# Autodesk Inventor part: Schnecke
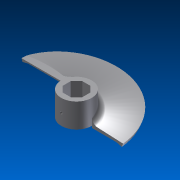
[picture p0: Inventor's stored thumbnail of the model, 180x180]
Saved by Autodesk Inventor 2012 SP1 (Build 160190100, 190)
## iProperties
Created: 2012-02
Part Number: Schnecke
Material: Default
Document SubType Name: Modeling
Designer: MP
Mass: 7789.64 g
Surface Area: 6560.61 cm^2
Volume: 7789.64 cm^3
Density: 1 g/cm^3
Author: MP
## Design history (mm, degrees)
sketch "Skizze1"
  geometry: L1 (0, 0)-(0, 200); L2 (0, 10)-(-285, 10); L3 (-285, 10)-(-325, 0); L4 (-325, 0)-(-334.295, 25); L5 (-334.295, 25)-(-110, 35); L6 (-110, 35)-(-110, 10); L7 (-110, 35)-(-110, 200); L8 (-110, 200)-(0, 200); L9 (-285, 10)-(-328.718, 10); L10 (-110, 35)-(0, 39.904); L11 (-25, 38.79)-(-25, 10); L12 (0, 25)-(-110, 25); 1 further point
  constraints: 24 end point, 9 point on line, 5 perpendicular, 2 collinear, 2 horizontal alignment, 1 parallel, 1 vertical
  dimensions: "d0" = 200 distance of L1.start L1.end; "d1" = 650 diameter of L3.end L1; "d3" = 570 diameter of L2.end L1 (computed from d1); "d4" = 795 diameter of point (-397.5, 195) L1; "d5" = 195 vertical distance of point (-397.5, 195) L3.end; "d6" = 220 diameter of L5.end L1; "d7" = 25 distance from line of L2 L5.end; "d8" = 10 vertical distance of L4.end L5.end (= d9); "d9" = 10 distance from line of L9 L3.end; "d10" = 20.3949 deg angle of L4 L1 (derived); "d32" = 50 diameter of L11 L1
feature "Spirale1" pitch "d11" = 350; turns "d13" = 0.5; dims "d12" = 10, "d14" = 3.55958 (= d10), angle "d15" = 90 deg, angle "d16" = 90 deg, "d17" = 0, "d18" = 0
revolve "Umdrehung2" stored, may be unused: angle "d33" = 90 deg
workplane "Arbeitsebene1"
sketch "Skizze3"
  geometry: L1 (139.409, 71)-(181, 29.409); L2 (181, 29.409)-(181, -29.409); L3 (181, -29.409)-(139.409, -71); L4 (139.409, -71)-(80.591, -71); L5 (80.591, -71)-(39, -29.409); L6 (39, -29.409)-(39, 29.409); L7 (39, 29.409)-(80.591, 71); L8 (80.591, 71)-(139.409, 71); 6 further points
  constraints: 16 end point, 3 coincident, 2 horizontal alignment, 1 horizontal, 21 other
  dimensions: "d41" = 142 distance between parallel lines of L4 L8
extrude "Extrusion1" cut sketch "Skizze3" stored distance "d35" = 10; taper "d36" = 0 deg
extrude "Extrusion2" cut sketch "Skizze3" stored distance "d37" = 10; taper "d38" = 0 deg
feature "Fläche löschen1"
fillet "Rundung1" dims "d39" = 40
fillet "Rundung2" dims "d40" = 30
extrude "Extrusion3" cut sketch "Skizze3" stored distance "d42" = 10; taper "d43" = 0 deg
workplane "Arbeitsebene2"
sketch "Skizze4"
  geometry: L1 (110, -5)-(-110, -5) reference; L2 (0, -79.909)-(0, 249.362) reference; 3 further points
  constraints: 1 point on line
  dimensions: "d44" = 80 distance from line of point (0, 75) L1
hole "Bohrung1" sketch "Skizze4" at (0, 75) diameter "d45" = 17.294; stored, may be unused: countersink angle "d49" = 90 deg, drill point angle "d51" = 118 deg; dims "d46" = 6, "d47" = 4, "d48" = 2, "d50" = 8
feature "Fläche verschieben1" dims "d52" = -2
node "Volumenkörper1"
other parameters: "d34" = -5
